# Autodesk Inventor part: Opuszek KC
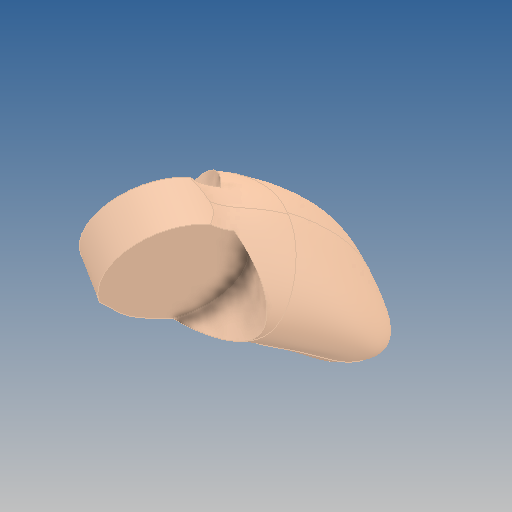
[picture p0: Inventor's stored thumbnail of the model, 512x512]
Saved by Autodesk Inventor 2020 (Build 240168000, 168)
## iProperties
Created: 2019-10
Part Number: Opuszek KC
Material: GFRP
Document SubType Name: Modeling
Designer: yello
Density: 1.75 g/cm^3
Appearance: Default
Author: yello
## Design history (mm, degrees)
feature "Opuszek KC"
body "Solid1"
